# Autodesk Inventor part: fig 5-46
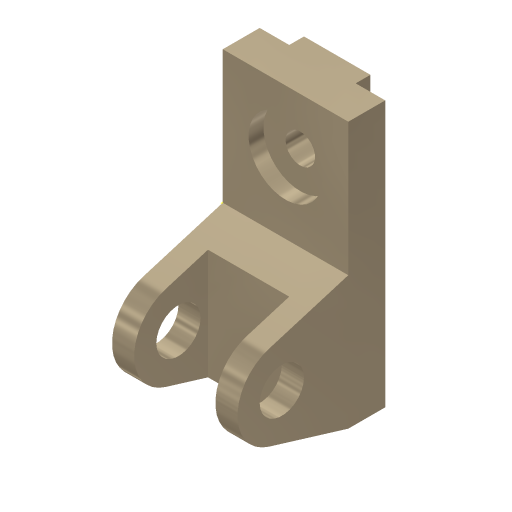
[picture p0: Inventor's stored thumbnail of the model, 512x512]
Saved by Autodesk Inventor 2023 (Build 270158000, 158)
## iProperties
Created: 2001-11
Part Number: fig 5-46
Document SubType Name: Modeling
Designer: Renu Muthoo
Density: 1 g/cm^3
Material: Generic
Appearance: Metal-Titanium (Polished)
Control State: 0
Master: False
Checked Out: False
Shininess: 65.0
Angle Display Precision: 2
Document Length Units: 11269
Document Angle Units: 11279
Document Time Units: 11290
Document Mass Units: 11283
Document Length Units Precision: 3
Document Angle Units Precision: 2
Density: 0.0
Volumn: 0.0
Area: 0.0
PropertySet Name: Model Information
Author: Renu Muthoo
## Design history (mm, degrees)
node "Sketch1"
sketch "Sketch2"
  geometry: L1 (33.257, 104.664)-(33.257, -75.336); L2 (33.257, -75.336)-(8.257, -75.336); L3 (8.257, -75.336)-(-45.451, -59.045); L4 (-45.451, -1.628)-(8.257, 14.664); L5 (8.257, 14.664)-(8.257, 104.664); L6 (8.257, 104.664)-(33.257, 104.664); C1 r 15 at (-36.743, -30.336); A1 r 30 centre (-36.743, -30.336) between (-45.451, -1.628) and (-45.451, -59.045)
  constraints: 12 end point, 2 centre point, 2 equal length, 2 parallel, 2 point on circle, 2 tangent, 1 coincident, 1 perpendicular, 1 vertical
  dimensions: "d0" = 180 distance of L1.start L1.end; "d1" = 30 radius of A1; "d2" = 25 distance of L5.end L1.start; "d3" = 45 distance from line of L2 A1.centre; "d4" = 70 distance from line of L1 A1.centre; "d5" = 30 diameter of C1
extrude "Extrusion1" new body sketch "Sketch2" distance "d6" = 85; taper "d7" = 0 deg
workplane "Work Plane1"
sketch "Sketch3"
  geometry: L1 (15, 62.364)-(70, 62.364); L2 (70, 62.364)-(70, -52.386); L3 (70, -52.386)-(15, -52.386); L4 (15, -52.386)-(15, 62.364); L5 (0, -45)-(0, -28.708) reference
  constraints: 8 end point, 2 parallel, 1 horizontal, 1 perpendicular
  dimensions: "d8" = 55 distance of L1.start L1.end; "d9" = 15 distance between parallel lines of L5 L4
extrude "Extrusion2" cut sketch "Sketch3" distance "d10" = 50; taper "d11" = 0 deg
sketch "Sketch4"
  geometry: L1 (0, 25)-(85, 25) reference; L2 (0, 0)-(0, 25) reference; L3 (20, 25)-(65, 25); L4 (65, 25)-(65, 35); L5 (65, 35)-(20, 35); L6 (20, 35)-(20, 25)
  constraints: 8 end point, 2 parallel, 1 horizontal, 1 perpendicular, 1 point on line
  dimensions: "d12" = 45 distance of L4.end L5.end; "d13" = 10 distance of L3.end L4.end; "d14" = 20 distance between parallel lines of L2 L6
extrude "Extrusion3" join sketch "Sketch4" stored distance "d15" = 50; taper "d16" = 0 deg
sketch "Sketch5"
  geometry: L1 (85, 0)-(85, 90) reference; L2 (0, 90)-(85, 90) reference; 1 further point
  dimensions: "d17" = 42 distance from line of L2 point (42.5, 48); "d18" = 42.5 distance from line of L1 point (42.5, 48)
hole "Hole1" sketch "Sketch5" at (42.5, 48) diameter "d19" = 20; stored, may be unused: countersink angle "d23" = 82 deg, drill point angle "d25" = 118 deg; dims "d20" = 6, "d21" = 50, "d22" = 10, "d24" = 8
workpoint "Work Point5"
body "Solid1"
